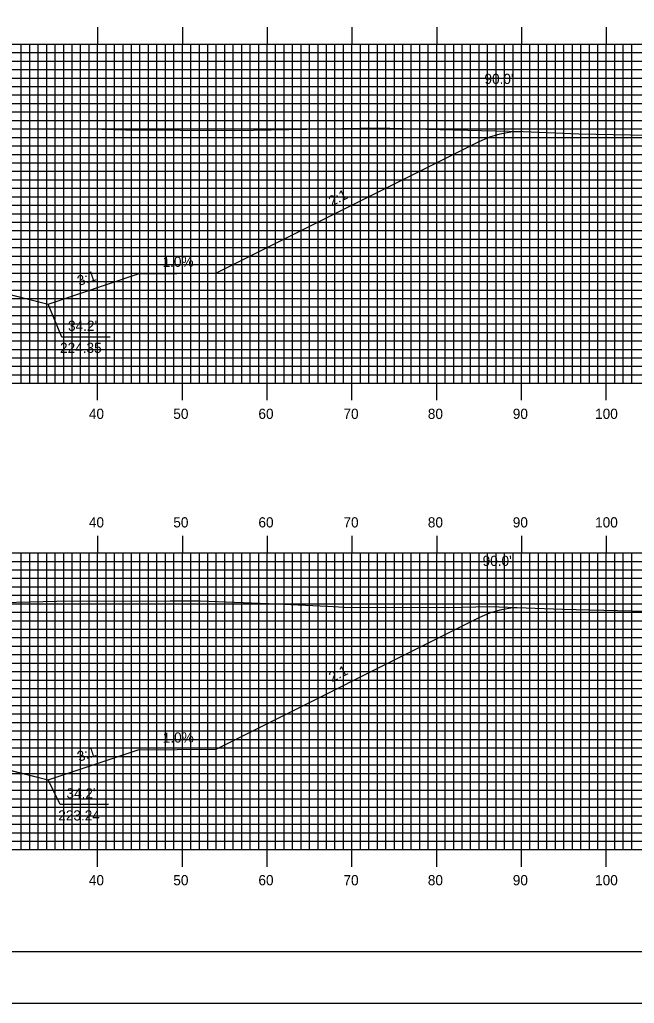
# Model space of a CAD drawing. Extents: x 1817276 to 1817620, y 442591 to 442811.
# Drawn here: x 1817472.9 to 1817545.4, y 442590.5 to 442706.6 of the extents above; entities that cross this region are included whole.
import ezdxf

# ---------------------------------------------------------------- set-up
doc = ezdxf.new("R2010")
doc.units = 0
for name, color, linetype in [('ANNOTATION', 7, 'Continuous'), ('BORDER', 7, 'Continuous'), ('D_Roadway_Centerline', 7, 'Continuous'), ('D_Roadway_SlopeLines', 7, 'Continuous'), ('D_Text_Standard', 7, 'Continuous'), ('H_V ANNOTATION', 7, 'Continuous'), ('MAJOR', 7, 'Continuous'), ('MINOR', 7, 'Continuous'), ('PLOT BOUNDARY', 7, 'Continuous'), ('S_Roadway_Centerline', 7, 'Continuous')]:
    doc.layers.add(name, color=color, linetype=linetype)

msp = doc.modelspace()

# ---------------------------------------------------------------- linework, layer by layer
at = {"layer": 'ANNOTATION'}
for points in [[(1817483.57, 442669.12), (1817477.88, 442669.12), (1817476.27, 442673.01)], [(1817483.39, 442613.99), (1817477.69, 442613.99), (1817476.27, 442616.91)]]:
    msp.add_lwpolyline(points, dxfattribs=at)
at = {"layer": 'BORDER'}
msp.add_lwpolyline([(1817292.5, 442596.67), (1817612.5, 442596.67), (1817612.5, 442806.67), (1817292.5, 442806.67)], close=True, dxfattribs=at)
at = {"layer": 'D_Roadway_Centerline'}
for points in [[(1817352.1, 442690.39), (1817353.35, 442690.39), (1817354.6, 442690.2), (1817355.85, 442689.84), (1817357.1, 442689.31), (1817382.3, 442676.71), (1817397.29, 442676.56), (1817407.93, 442673.01), (1817411.93, 442674.01), (1817422.1, 442676.56), (1817430.1, 442676.88), (1817442.1, 442677.12), (1817454.1, 442676.88), (1817462.1, 442676.56), (1817472.27, 442674.01), (1817476.27, 442673.01), (1817486.9, 442676.56), (1817496.05, 442676.65), (1817527.1, 442692.17), (1817528.35, 442692.72), (1817529.6, 442693.1), (1817530.85, 442693.31), (1817532.1, 442693.37)], [(1817352.1, 442636.54), (1817353.35, 442636.48), (1817354.6, 442636.26), (1817355.85, 442635.88), (1817357.1, 442635.33), (1817386.65, 442620.56), (1817397.29, 442620.45), (1817407.93, 442616.91), (1817411.93, 442617.91), (1817422.1, 442620.45), (1817430.1, 442620.77), (1817442.1, 442621.01), (1817454.1, 442620.77), (1817462.1, 442620.45), (1817472.27, 442617.91), (1817476.27, 442616.91), (1817486.9, 442620.45), (1817496.1, 442620.54), (1817527.1, 442636.04), (1817528.35, 442636.58), (1817529.6, 442636.96), (1817530.85, 442637.17), (1817532.1, 442637.21)]]:
    msp.add_lwpolyline(points, dxfattribs=at)
at = {"layer": 'D_Roadway_SlopeLines'}
for points in [[(1817486.9, 442676.56), (1817496.05, 442676.65), (1817527.1, 442692.17), (1817528.35, 442692.72), (1817529.6, 442693.1), (1817530.85, 442693.31), (1817532.1, 442693.37)], [(1817462.1, 442676.56), (1817476.27, 442673.01)], [(1817476.27, 442673.01), (1817486.9, 442676.56)], [(1817486.9, 442620.45), (1817496.1, 442620.54), (1817527.1, 442636.04), (1817528.35, 442636.58), (1817529.6, 442636.96), (1817530.85, 442637.17), (1817532.1, 442637.21)], [(1817462.1, 442620.45), (1817476.27, 442616.91)], [(1817476.27, 442616.91), (1817486.9, 442620.45)]]:
    msp.add_lwpolyline(points, dxfattribs=at)
at = {"layer": 'MAJOR'}
for p, q in [((1817482.1, 442705.67), (1817482.1, 442703.67)), ((1817492.1, 442705.67), (1817492.1, 442703.67)), ((1817502.1, 442705.67), (1817502.1, 442703.67)), ((1817512.1, 442705.67), (1817512.1, 442703.67)), ((1817522.1, 442705.67), (1817522.1, 442703.67)), ((1817532.1, 442705.67), (1817532.1, 442703.67)), ((1817542.1, 442705.67), (1817542.1, 442703.67)), ((1817302.1, 442703.67), (1817582.1, 442703.67)), ((1817302.1, 442703.67), (1817582.1, 442703.67)), ((1817482.1, 442663.67), (1817482.1, 442703.67)), ((1817492.1, 442663.67), (1817492.1, 442703.67)), ((1817502.1, 442663.67), (1817502.1, 442703.67)), ((1817512.1, 442663.67), (1817512.1, 442703.67)), ((1817522.1, 442663.67), (1817522.1, 442703.67)), ((1817532.1, 442663.67), (1817532.1, 442703.67)), ((1817542.1, 442663.67), (1817542.1, 442703.67)), ((1817302.1, 442698.67), (1817582.1, 442698.67)), ((1817302.1, 442693.67), (1817582.1, 442693.67)), ((1817302.1, 442688.67), (1817582.1, 442688.67)), ((1817302.1, 442683.67), (1817582.1, 442683.67)), ((1817302.1, 442678.67), (1817582.1, 442678.67)), ((1817302.1, 442673.67), (1817582.1, 442673.67)), ((1817302.1, 442668.67), (1817582.1, 442668.67)), ((1817302.1, 442663.67), (1817582.1, 442663.67)), ((1817302.1, 442663.67), (1817582.1, 442663.67)), ((1817482.1, 442661.66), (1817482.1, 442663.67)), ((1817492.1, 442661.66), (1817492.1, 442663.67)), ((1817502.1, 442661.66), (1817502.1, 442663.67)), ((1817512.1, 442661.66), (1817512.1, 442663.67)), ((1817522.1, 442661.66), (1817522.1, 442663.67)), ((1817532.1, 442661.66), (1817532.1, 442663.67)), ((1817542.1, 442661.66), (1817542.1, 442663.67)), ((1817482.1, 442645.67), (1817482.1, 442643.67)), ((1817492.1, 442645.67), (1817492.1, 442643.67)), ((1817502.1, 442645.67), (1817502.1, 442643.67)), ((1817512.1, 442645.67), (1817512.1, 442643.67)), ((1817522.1, 442645.67), (1817522.1, 442643.67)), ((1817532.1, 442645.67), (1817532.1, 442643.67)), ((1817542.1, 442645.67), (1817542.1, 442643.67)), ((1817302.1, 442643.67), (1817582.1, 442643.67)), ((1817302.1, 442643.67), (1817582.1, 442643.67)), ((1817482.1, 442608.67), (1817482.1, 442643.67)), ((1817492.1, 442608.67), (1817492.1, 442643.67)), ((1817502.1, 442608.67), (1817502.1, 442643.67)), ((1817512.1, 442608.67), (1817512.1, 442643.67)), ((1817522.1, 442608.67), (1817522.1, 442643.67)), ((1817532.1, 442608.67), (1817532.1, 442643.67)), ((1817542.1, 442608.67), (1817542.1, 442643.67)), ((1817302.1, 442638.67), (1817582.1, 442638.67)), ((1817302.1, 442633.67), (1817582.1, 442633.67)), ((1817302.1, 442628.67), (1817582.1, 442628.67)), ((1817302.1, 442623.67), (1817582.1, 442623.67)), ((1817302.1, 442618.67), (1817582.1, 442618.67)), ((1817302.1, 442613.67), (1817582.1, 442613.67)), ((1817302.1, 442608.67), (1817582.1, 442608.67)), ((1817302.1, 442608.67), (1817582.1, 442608.67)), ((1817482.1, 442606.66), (1817482.1, 442608.67)), ((1817492.1, 442606.66), (1817492.1, 442608.67)), ((1817502.1, 442606.66), (1817502.1, 442608.67)), ((1817512.1, 442606.66), (1817512.1, 442608.67)), ((1817522.1, 442606.66), (1817522.1, 442608.67)), ((1817532.1, 442606.66), (1817532.1, 442608.67)), ((1817542.1, 442606.66), (1817542.1, 442608.67))]:
    msp.add_line(p, q, dxfattribs=at)
at = {"layer": 'MINOR'}
for p, q in [((1817473.1, 442663.67), (1817473.1, 442703.67)), ((1817474.1, 442663.67), (1817474.1, 442703.67)), ((1817475.1, 442663.67), (1817475.1, 442703.67)), ((1817476.1, 442663.67), (1817476.1, 442703.67)), ((1817477.1, 442663.67), (1817477.1, 442703.67)), ((1817478.1, 442663.67), (1817478.1, 442703.67)), ((1817479.1, 442663.67), (1817479.1, 442703.67)), ((1817480.1, 442663.67), (1817480.1, 442703.67)), ((1817481.1, 442663.67), (1817481.1, 442703.67)), ((1817483.1, 442663.67), (1817483.1, 442703.67)), ((1817484.1, 442663.67), (1817484.1, 442703.67)), ((1817485.1, 442663.67), (1817485.1, 442703.67)), ((1817486.1, 442663.67), (1817486.1, 442703.67)), ((1817487.1, 442663.67), (1817487.1, 442703.67)), ((1817488.1, 442663.67), (1817488.1, 442703.67)), ((1817489.1, 442663.67), (1817489.1, 442703.67)), ((1817490.1, 442663.67), (1817490.1, 442703.67)), ((1817491.1, 442663.67), (1817491.1, 442703.67)), ((1817493.1, 442663.67), (1817493.1, 442703.67)), ((1817494.1, 442663.67), (1817494.1, 442703.67)), ((1817495.1, 442663.67), (1817495.1, 442703.67)), ((1817496.1, 442663.67), (1817496.1, 442703.67)), ((1817497.1, 442663.67), (1817497.1, 442703.67)), ((1817498.1, 442663.67), (1817498.1, 442703.67)), ((1817499.1, 442663.67), (1817499.1, 442703.67)), ((1817500.1, 442663.67), (1817500.1, 442703.67)), ((1817501.1, 442663.67), (1817501.1, 442703.67)), ((1817503.1, 442663.67), (1817503.1, 442703.67)), ((1817504.1, 442663.67), (1817504.1, 442703.67)), ((1817505.1, 442663.67), (1817505.1, 442703.67)), ((1817506.1, 442663.67), (1817506.1, 442703.67)), ((1817507.1, 442663.67), (1817507.1, 442703.67)), ((1817508.1, 442663.67), (1817508.1, 442703.67)), ((1817509.1, 442663.67), (1817509.1, 442703.67)), ((1817510.1, 442663.67), (1817510.1, 442703.67)), ((1817511.1, 442663.67), (1817511.1, 442703.67)), ((1817513.1, 442663.67), (1817513.1, 442703.67)), ((1817514.1, 442663.67), (1817514.1, 442703.67)), ((1817515.1, 442663.67), (1817515.1, 442703.67)), ((1817516.1, 442663.67), (1817516.1, 442703.67)), ((1817517.1, 442663.67), (1817517.1, 442703.67)), ((1817518.1, 442663.67), (1817518.1, 442703.67)), ((1817519.1, 442663.67), (1817519.1, 442703.67)), ((1817520.1, 442663.67), (1817520.1, 442703.67)), ((1817521.1, 442663.67), (1817521.1, 442703.67)), ((1817523.1, 442663.67), (1817523.1, 442703.67)), ((1817524.1, 442663.67), (1817524.1, 442703.67)), ((1817525.1, 442663.67), (1817525.1, 442703.67)), ((1817526.1, 442663.67), (1817526.1, 442703.67)), ((1817527.1, 442663.67), (1817527.1, 442703.67)), ((1817528.1, 442663.67), (1817528.1, 442703.67)), ((1817529.1, 442663.67), (1817529.1, 442703.67)), ((1817530.1, 442663.67), (1817530.1, 442703.67)), ((1817531.1, 442663.67), (1817531.1, 442703.67)), ((1817533.1, 442663.67), (1817533.1, 442703.67)), ((1817534.1, 442663.67), (1817534.1, 442703.67)), ((1817535.1, 442663.67), (1817535.1, 442703.67)), ((1817536.1, 442663.67), (1817536.1, 442703.67)), ((1817537.1, 442663.67), (1817537.1, 442703.67)), ((1817538.1, 442663.67), (1817538.1, 442703.67)), ((1817539.1, 442663.67), (1817539.1, 442703.67)), ((1817540.1, 442663.67), (1817540.1, 442703.67)), ((1817541.1, 442663.67), (1817541.1, 442703.67)), ((1817543.1, 442663.67), (1817543.1, 442703.67)), ((1817544.1, 442663.67), (1817544.1, 442703.67)), ((1817545.1, 442663.67), (1817545.1, 442703.67)), ((1817302.1, 442702.67), (1817582.1, 442702.67)), ((1817302.1, 442701.67), (1817582.1, 442701.67)), ((1817302.1, 442700.67), (1817582.1, 442700.67)), ((1817302.1, 442699.67), (1817582.1, 442699.67)), ((1817302.1, 442697.67), (1817582.1, 442697.67)), ((1817302.1, 442696.67), (1817582.1, 442696.67)), ((1817302.1, 442695.67), (1817582.1, 442695.67)), ((1817302.1, 442694.67), (1817582.1, 442694.67)), ((1817302.1, 442692.67), (1817582.1, 442692.67)), ((1817302.1, 442691.67), (1817582.1, 442691.67)), ((1817302.1, 442690.67), (1817582.1, 442690.67)), ((1817302.1, 442689.67), (1817582.1, 442689.67)), ((1817302.1, 442687.67), (1817582.1, 442687.67)), ((1817302.1, 442686.67), (1817582.1, 442686.67)), ((1817302.1, 442685.67), (1817582.1, 442685.67)), ((1817302.1, 442684.67), (1817582.1, 442684.67)), ((1817302.1, 442682.67), (1817582.1, 442682.67)), ((1817302.1, 442681.67), (1817582.1, 442681.67)), ((1817302.1, 442680.67), (1817582.1, 442680.67)), ((1817302.1, 442679.67), (1817582.1, 442679.67)), ((1817302.1, 442677.67), (1817582.1, 442677.67)), ((1817302.1, 442676.67), (1817582.1, 442676.67)), ((1817302.1, 442675.67), (1817582.1, 442675.67)), ((1817302.1, 442674.67), (1817582.1, 442674.67)), ((1817302.1, 442672.67), (1817582.1, 442672.67)), ((1817302.1, 442671.67), (1817582.1, 442671.67)), ((1817302.1, 442670.67), (1817582.1, 442670.67)), ((1817302.1, 442669.67), (1817582.1, 442669.67)), ((1817302.1, 442667.67), (1817582.1, 442667.67)), ((1817302.1, 442666.67), (1817582.1, 442666.67)), ((1817302.1, 442665.67), (1817582.1, 442665.67)), ((1817302.1, 442664.67), (1817582.1, 442664.67)), ((1817302.1, 442642.67), (1817582.1, 442642.67)), ((1817473.1, 442608.67), (1817473.1, 442643.67)), ((1817474.1, 442608.67), (1817474.1, 442643.67)), ((1817475.1, 442608.67), (1817475.1, 442643.67)), ((1817476.1, 442608.67), (1817476.1, 442643.67)), ((1817477.1, 442608.67), (1817477.1, 442643.67)), ((1817478.1, 442608.67), (1817478.1, 442643.67)), ((1817479.1, 442608.67), (1817479.1, 442643.67)), ((1817480.1, 442608.67), (1817480.1, 442643.67)), ((1817481.1, 442608.67), (1817481.1, 442643.67)), ((1817483.1, 442608.67), (1817483.1, 442643.67)), ((1817484.1, 442608.67), (1817484.1, 442643.67)), ((1817485.1, 442608.67), (1817485.1, 442643.67)), ((1817486.1, 442608.67), (1817486.1, 442643.67)), ((1817487.1, 442608.67), (1817487.1, 442643.67)), ((1817488.1, 442608.67), (1817488.1, 442643.67)), ((1817489.1, 442608.67), (1817489.1, 442643.67)), ((1817490.1, 442608.67), (1817490.1, 442643.67)), ((1817491.1, 442608.67), (1817491.1, 442643.67)), ((1817493.1, 442608.67), (1817493.1, 442643.67)), ((1817494.1, 442608.67), (1817494.1, 442643.67)), ((1817495.1, 442608.67), (1817495.1, 442643.67)), ((1817496.1, 442608.67), (1817496.1, 442643.67)), ((1817497.1, 442608.67), (1817497.1, 442643.67)), ((1817498.1, 442608.67), (1817498.1, 442643.67)), ((1817499.1, 442608.67), (1817499.1, 442643.67)), ((1817500.1, 442608.67), (1817500.1, 442643.67)), ((1817501.1, 442608.67), (1817501.1, 442643.67)), ((1817503.1, 442608.67), (1817503.1, 442643.67)), ((1817504.1, 442608.67), (1817504.1, 442643.67)), ((1817505.1, 442608.67), (1817505.1, 442643.67)), ((1817506.1, 442608.67), (1817506.1, 442643.67)), ((1817507.1, 442608.67), (1817507.1, 442643.67)), ((1817508.1, 442608.67), (1817508.1, 442643.67)), ((1817509.1, 442608.67), (1817509.1, 442643.67)), ((1817510.1, 442608.67), (1817510.1, 442643.67)), ((1817511.1, 442608.67), (1817511.1, 442643.67)), ((1817513.1, 442608.67), (1817513.1, 442643.67)), ((1817514.1, 442608.67), (1817514.1, 442643.67)), ((1817515.1, 442608.67), (1817515.1, 442643.67)), ((1817516.1, 442608.67), (1817516.1, 442643.67)), ((1817517.1, 442608.67), (1817517.1, 442643.67)), ((1817518.1, 442608.67), (1817518.1, 442643.67)), ((1817519.1, 442608.67), (1817519.1, 442643.67)), ((1817520.1, 442608.67), (1817520.1, 442643.67)), ((1817521.1, 442608.67), (1817521.1, 442643.67)), ((1817523.1, 442608.67), (1817523.1, 442643.67)), ((1817524.1, 442608.67), (1817524.1, 442643.67)), ((1817525.1, 442608.67), (1817525.1, 442643.67)), ((1817526.1, 442608.67), (1817526.1, 442643.67)), ((1817527.1, 442608.67), (1817527.1, 442643.67)), ((1817528.1, 442608.67), (1817528.1, 442643.67)), ((1817529.1, 442608.67), (1817529.1, 442643.67)), ((1817530.1, 442608.67), (1817530.1, 442643.67)), ((1817531.1, 442608.67), (1817531.1, 442643.67)), ((1817533.1, 442608.67), (1817533.1, 442643.67)), ((1817534.1, 442608.67), (1817534.1, 442643.67)), ((1817535.1, 442608.67), (1817535.1, 442643.67)), ((1817536.1, 442608.67), (1817536.1, 442643.67)), ((1817537.1, 442608.67), (1817537.1, 442643.67)), ((1817538.1, 442608.67), (1817538.1, 442643.67)), ((1817539.1, 442608.67), (1817539.1, 442643.67)), ((1817540.1, 442608.67), (1817540.1, 442643.67)), ((1817541.1, 442608.67), (1817541.1, 442643.67)), ((1817543.1, 442608.67), (1817543.1, 442643.67)), ((1817544.1, 442608.67), (1817544.1, 442643.67)), ((1817545.1, 442608.67), (1817545.1, 442643.67)), ((1817302.1, 442641.67), (1817582.1, 442641.67)), ((1817302.1, 442640.67), (1817582.1, 442640.67)), ((1817302.1, 442639.67), (1817582.1, 442639.67)), ((1817302.1, 442637.67), (1817582.1, 442637.67)), ((1817302.1, 442636.67), (1817582.1, 442636.67)), ((1817302.1, 442635.67), (1817582.1, 442635.67)), ((1817302.1, 442634.67), (1817582.1, 442634.67)), ((1817302.1, 442632.67), (1817582.1, 442632.67)), ((1817302.1, 442631.67), (1817582.1, 442631.67)), ((1817302.1, 442630.67), (1817582.1, 442630.67)), ((1817302.1, 442629.67), (1817582.1, 442629.67)), ((1817302.1, 442627.67), (1817582.1, 442627.67)), ((1817302.1, 442626.67), (1817582.1, 442626.67)), ((1817302.1, 442625.67), (1817582.1, 442625.67)), ((1817302.1, 442624.67), (1817582.1, 442624.67)), ((1817302.1, 442622.67), (1817582.1, 442622.67)), ((1817302.1, 442621.67), (1817582.1, 442621.67)), ((1817302.1, 442620.67), (1817582.1, 442620.67)), ((1817302.1, 442619.67), (1817582.1, 442619.67)), ((1817302.1, 442617.67), (1817582.1, 442617.67)), ((1817302.1, 442616.67), (1817582.1, 442616.67)), ((1817302.1, 442615.67), (1817582.1, 442615.67)), ((1817302.1, 442614.67), (1817582.1, 442614.67)), ((1817302.1, 442612.67), (1817582.1, 442612.67)), ((1817302.1, 442611.67), (1817582.1, 442611.67)), ((1817302.1, 442610.67), (1817582.1, 442610.67)), ((1817302.1, 442609.67), (1817582.1, 442609.67))]:
    msp.add_line(p, q, dxfattribs=at)
at = {"layer": 'PLOT BOUNDARY'}
msp.add_lwpolyline([(1817276.31, 442590.55), (1817616.31, 442590.55), (1817616.31, 442810.55), (1817276.31, 442810.55)], close=True, dxfattribs=at)
at = {"layer": 'S_Roadway_Centerline'}
for points in [[(1817472.07, 442693.71), (1817481.2, 442693.66), (1817485.38, 442693.56), (1817498.3, 442693.48), (1817500.5, 442693.51), (1817515.15, 442693.81), (1817520.85, 442693.62), (1817532.3, 442693.36), (1817538.85, 442693.07), (1817549.01, 442692.91), (1817551.99, 442692.87), (1817564.51, 442692.59), (1817565.74, 442692.57), (1817566.02, 442692.56), (1817578.57, 442691.87), (1817581.69, 442691.86), (1817582.1, 442691.85)], [(1817467.72, 442637.74), (1817477.24, 442637.99), (1817490.64, 442638.02), (1817494.21, 442638.03), (1817502.31, 442637.69), (1817509.21, 442637.37), (1817511.17, 442637.28), (1817523.44, 442637.21), (1817528.38, 442637.33), (1817536.93, 442637.05), (1817545.03, 442636.83), (1817549.79, 442636.8), (1817567.89, 442636.37), (1817579.8, 442635.99), (1817582.1, 442635.93)]]:
    msp.add_lwpolyline(points, dxfattribs=at)

# ---------------------------------------------------------------- texts
at = {"layer": 'ANNOTATION'}
for s, rotation, p in [('2:1', 26.5651, (1817509.72, 442684.52)), ('1.0%', 0.5729, (1817489.77, 442677.39)), ('3:1', 18.4349, (1817479.93, 442675.14)), ('2:1', 26.5651, (1817509.75, 442628.4)), ('1.0%', 0.5729, (1817489.79, 442621.28)), ('3:1', 18.4349, (1817479.93, 442619.03))]:
    msp.add_text(s, height=1.2, rotation=rotation, dxfattribs=at).set_placement(p)
for s, p in [("34.2'", (1817478.61, 442669.85)), ('224.35', (1817477.67, 442667.25)), ("34.2'", (1817478.43, 442614.71)), ('223.24', (1817477.46, 442612.11))]:
    msp.add_text(s, height=1.2, dxfattribs=at).set_placement(p)
at = {"layer": 'D_Text_Standard'}
for p in [(1817527.73, 442698.97), (1817527.51, 442642.13)]:
    msp.add_text("90.0'", height=1.2, dxfattribs=at).set_placement(p)
at = {"layer": 'H_V ANNOTATION'}
for s, p in [('40', (1817481.07, 442659.47)), ('50', (1817491.03, 442659.47)), ('60', (1817501.07, 442659.47)), ('70', (1817511.1, 442659.47)), ('80', (1817521.05, 442659.47)), ('90', (1817531.07, 442659.47)), ('100', (1817540.78, 442659.47)), ('40', (1817481.07, 442646.67)), ('50', (1817491.03, 442646.67)), ('60', (1817501.07, 442646.67)), ('70', (1817511.1, 442646.67)), ('80', (1817521.05, 442646.67)), ('90', (1817531.07, 442646.67)), ('100', (1817540.78, 442646.67)), ('40', (1817481.07, 442604.47)), ('50', (1817491.03, 442604.47)), ('60', (1817501.07, 442604.47)), ('70', (1817511.1, 442604.47)), ('80', (1817521.05, 442604.47)), ('90', (1817531.07, 442604.47)), ('100', (1817540.78, 442604.47))]:
    msp.add_text(s, height=1.2, dxfattribs=at).set_placement(p)

doc.saveas('drawing.dxf')
